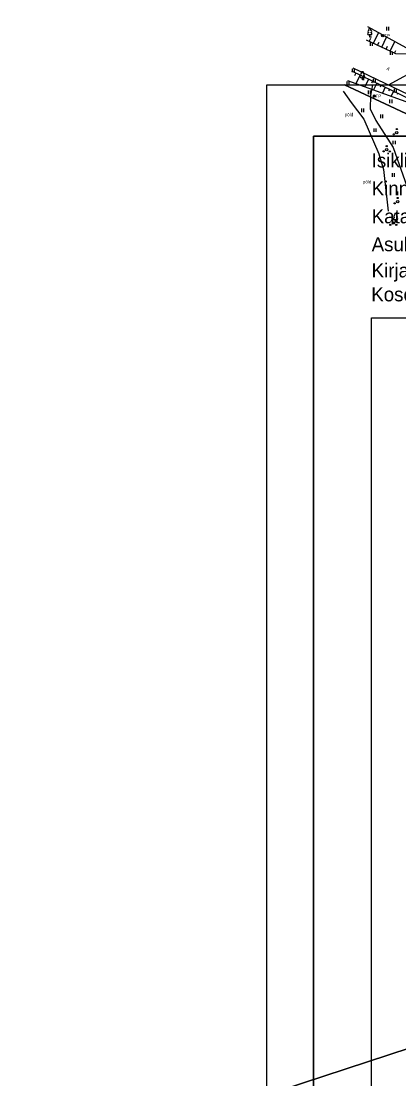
# Model space of a CAD drawing. Extents: x 554947 to 555436, y 6564938 to 6565792.
# Drawn here: x 554946.6 to 555027.7, y 6565441.5 to 6565668.6 of the extents above; entities that cross this region are included whole.
import ezdxf

# ---------------------------------------------------------------- set-up
doc = ezdxf.new("R2010")
doc.units = 0
for name, color, linetype in [('HALJASTUS', 7, 'Continuous'), ('KPKAABEL', 7, 'Continuous'), ('PIIR', 7, 'Continuous'), ('POST', 7, 'Continuous'), ('PUU', 7, 'Continuous'), ('RELJEEF', 7, 'Continuous'), ('TEE', 7, 'Continuous'), ('VORMISTUS_2', 7, 'Continuous')]:
    doc.layers.add(name, color=color, linetype=linetype)

msp = doc.modelspace()

# ---------------------------------------------------------------- linework, layer by layer
at = {"layer": 'HALJASTUS'}
for p, q in [((555025.03, 6565667.38), (555025.03, 6565666.61)), ((555025.49, 6565667.38), (555025.49, 6565666.61)), ((555021.54, 6565664.03), (555021.54, 6565663.27)), ((555021.99, 6565664.03), (555021.99, 6565663.27)), ((555025.82, 6565662.1), (555025.82, 6565661.34)), ((555026.28, 6565662.1), (555026.28, 6565661.34)), ((555017.66, 6565658.36), (555017.66, 6565657.6)), ((555018.12, 6565658.36), (555018.12, 6565657.6)), ((555016.51, 6565655.6), (555016.51, 6565654.84)), ((555016.97, 6565655.6), (555016.97, 6565654.84)), ((555022.17, 6565656.19), (555022.17, 6565655.43)), ((555022.62, 6565656.19), (555022.62, 6565655.43)), ((555021.12, 6565653.67), (555021.12, 6565652.9)), ((555021.58, 6565653.67), (555021.58, 6565652.9)), ((555026.67, 6565654.02), (555026.67, 6565653.26)), ((555027.13, 6565654.02), (555027.13, 6565653.26)), ((555025.73, 6565651.73), (555025.73, 6565650.97)), ((555026.19, 6565651.73), (555026.19, 6565650.97)), ((555019.68, 6565649.8), (555019.68, 6565649.04)), ((555020.14, 6565649.8), (555020.14, 6565649.04)), ((555023.73, 6565648.51), (555023.73, 6565647.75)), ((555024.19, 6565648.51), (555024.19, 6565647.75)), ((555022.32, 6565645.56), (555022.32, 6565644.8)), ((555022.78, 6565645.56), (555022.78, 6565644.8)), ((555026.44, 6565642.9), (555026.44, 6565642.14)), ((555026.89, 6565642.9), (555026.89, 6565642.14)), ((555026.24, 6565635.94), (555026.24, 6565635.18)), ((555026.7, 6565635.94), (555026.7, 6565635.18)), ((555027.44, 6565631.98), (555027.44, 6565631.22))]:
    msp.add_line(p, q, dxfattribs=at)
msp.add_lwpolyline([(555015.75, 6565653.58), (555017.49, 6565651.12), (555020.22, 6565647.57), (555023.44, 6565640.12), (555024.39, 6565636.74), (555025.43, 6565627.79)], dxfattribs=at)
at = {"layer": 'KPKAABEL'}
msp.add_lwpolyline([(555022.08, 6565654.91), (555021.62, 6565652.63), (555021.53, 6565649.77), (555022.79, 6565647.23), (555026.48, 6565641.46), (555030.61, 6565629.73), (555035.38, 6565618.81), (555040.84, 6565608.06), (555047.09, 6565597.8), (555053.57, 6565587.29), (555056.07, 6565583.7), (555062.11, 6565572.67), (555068.25, 6565560.98), (555073.77, 6565549.85), (555080.11, 6565537.98), (555085.96, 6565527.61), (555092.4, 6565515.61), (555098.4, 6565504.54), (555104.64, 6565492.44), (555110.84, 6565480.82), (555116.7, 6565469.07), (555121.82, 6565458.12), (555126.89, 6565446.73), (555132.74, 6565435.39)], dxfattribs=at)
at = {"layer": 'PIIR'}
for points in [[(555016.05, 6565654.91), (555030.24, 6565648.23), (555043.11, 6565640.11), (555053.62, 6565632.14), (555056.61, 6565622.91), (555057.22, 6565600.73), (555060.42, 6565583.26), (555065.78, 6565566.7), (555076.76, 6565542.38), (555113.82, 6565475.68), (554946.63, 6565420.78), (554981.01, 6565316.76), (555160.07, 6565375.54), (555166.64, 6565360.5), (555167.67, 6565357.91)], [(555045.31, 6565654.91), (555047.17, 6565654.02), (555063.43, 6565647.29), (555056.61, 6565622.91), (555053.62, 6565632.14), (555043.11, 6565640.11), (555030.24, 6565648.23), (555016.05, 6565654.91)]]:
    msp.add_lwpolyline(points, dxfattribs=at)
msp.add_lwpolyline([(554981.01, 6565316.76), (554946.63, 6565420.78), (555113.82, 6565475.68), (555124.27, 6565454.45), (555144.16, 6565410.6), (555160.07, 6565375.54)], close=True, dxfattribs=at)
at = {"layer": 'POST'}
for centre, radius in [((555024.26, 6565665.45), 0.25), ((555024.26, 6565665.45), 0.225), ((555024.26, 6565665.45), 0.2), ((555024.26, 6565665.45), 0.175), ((555024.26, 6565665.45), 0.15), ((555024.26, 6565665.45), 0.125), ((555024.26, 6565665.45), 0.1), ((555024.26, 6565665.45), 0.075), ((555024.26, 6565665.45), 0.05), ((555024.26, 6565665.45), 0.025), ((555022.42, 6565652.48), 0.25), ((555022.42, 6565652.48), 0.225), ((555022.42, 6565652.48), 0.2), ((555022.42, 6565652.48), 0.175), ((555022.42, 6565652.48), 0.15), ((555022.42, 6565652.48), 0.125), ((555022.42, 6565652.48), 0.1), ((555022.42, 6565652.48), 0.075), ((555022.42, 6565652.48), 0.05), ((555022.42, 6565652.48), 0.025)]:
    msp.add_circle(centre, radius, dxfattribs=at)
at = {"layer": 'PUU'}
for p, q in [((555021.71, 6565665.65), (555021.23, 6565665.65)), ((555021.47, 6565665.17), (555021.47, 6565665.65)), ((555021.85, 6565665.17), (555021.47, 6565665.17)), ((555020.13, 6565656.42), (555019.65, 6565656.42)), ((555019.89, 6565655.95), (555019.89, 6565656.42)), ((555020.27, 6565655.95), (555019.89, 6565655.95)), ((555027.24, 6565625.93), (555026.76, 6565625.93)), ((555027, 6565625.46), (555027, 6565625.93)), ((555027.38, 6565625.46), (555027, 6565625.46))]:
    msp.add_line(p, q, dxfattribs=at)
for centre, radius in [((555027.26, 6565645.42), 0.125), ((555026.61, 6565644.3), 0.125), ((555027.26, 6565644.67), 0.25), ((555025.1, 6565640.99), 0.25), ((555025.1, 6565641.74), 0.125), ((555024.45, 6565640.62), 0.125), ((555025.75, 6565640.62), 0.125), ((555026.8, 6565629.48), 0.125), ((555027.45, 6565629.85), 0.25), ((555027.45, 6565630.6), 0.125), ((555026.51, 6565625.25), 0.25), ((555026.51, 6565626), 0.125), ((555025.86, 6565624.87), 0.125), ((555027.16, 6565624.87), 0.125)]:
    msp.add_circle(centre, radius, dxfattribs=at)
for centre, radius, start, end in [((555021.23, 6565665.88), 0.238, 90.0016, 269.3953), ((555021.3, 6565666.34), 0.233, 109.0217, 253.1415), ((555021.47, 6565666.69), 0.277, 332.5799, 207.4201), ((555021.64, 6565666.34), 0.233, 286.8508, 70.9859), ((555021.7, 6565665.88), 0.238, 270.6047, 89.9984), ((555019.65, 6565656.66), 0.238, 90.0016, 269.3953), ((555019.72, 6565657.12), 0.233, 109.0217, 253.1415), ((555019.89, 6565657.46), 0.277, 332.5799, 207.4201), ((555020.06, 6565657.12), 0.233, 286.8508, 70.9859), ((555020.13, 6565656.66), 0.238, 270.6047, 89.9984), ((555026.76, 6565626.17), 0.238, 90.0016, 269.3953), ((555026.83, 6565626.63), 0.233, 109.0217, 253.1415), ((555027, 6565626.98), 0.277, 332.5799, 207.4201), ((555027.17, 6565626.63), 0.233, 286.8508, 70.9859), ((555027.24, 6565626.17), 0.238, 270.6047, 89.9984)]:
    msp.add_arc(centre, radius, start, end, dxfattribs=at)
at = {"layer": 'RELJEEF'}
for p, q in [((555022.24, 6565663.83), (555023.31, 6565666.1)), ((555021.34, 6565664.25), (555021.66, 6565664.95)), ((555023.15, 6565663.4), (555023.46, 6565664.07)), ((555024.06, 6565662.98), (555025.07, 6565665.15)), ((555025.87, 6565662.13), (555026.83, 6565664.2)), ((555024.96, 6565662.56), (555025.26, 6565663.19)), ((555026.78, 6565661.71), (555027.06, 6565662.31)), ((555025.49, 6565654.91), (555036.81, 6565661.16)), ((555018.47, 6565657.45), (555018.19, 6565656.87)), ((555019.37, 6565657.02), (555018.48, 6565655.17)), ((555020.27, 6565656.58), (555020.02, 6565656.06)), ((555021.17, 6565656.15), (555020.37, 6565654.49)), ((555022.07, 6565655.72), (555021.85, 6565655.25)), ((555022.97, 6565655.28), (555022.26, 6565653.81)), ((555023.87, 6565654.85), (555023.67, 6565654.44)), ((555024.77, 6565654.41), (555024.16, 6565653.13)), ((555025.67, 6565653.98), (555025.5, 6565653.62)), ((555026.58, 6565653.55), (555026.05, 6565652.45)), ((555027.48, 6565653.11), (555027.33, 6565652.81))]:
    msp.add_line(p, q, dxfattribs=at)
for points in [[(555029.78, 6565668.58), (555030.58, 6565661.46), (555027.05, 6565661.58), (555020.79, 6565664.51)], [(555029.78, 6565668.58), (555030.08, 6565662.44), (555021.01, 6565667.34)], [(555017.57, 6565657.89), (555030.59, 6565651.61), (555041.81, 6565645.02), (555049.4, 6565639.13)], [(555016.65, 6565655.83), (555029.97, 6565651.05), (555041.06, 6565644.31), (555048.71, 6565638.55)]]:
    msp.add_lwpolyline(points, dxfattribs=at)
at = {"layer": 'TEE'}
msp.add_lwpolyline([(555017.83, 6565658.57), (555031.54, 6565651.99), (555031.85, 6565651.41), (555035.2, 6565649.62), (555035.88, 6565649.68), (555042.56, 6565645.53), (555050.24, 6565639.61)], dxfattribs=at)
at = {"layer": 'VORMISTUS_2'}
for points in [[(554999.36, 6565654.91), (555209.36, 6565654.91), (555209.36, 6565357.91), (554999.36, 6565357.91)], [(555009.36, 6565368.91), (555199.36, 6565368.91), (555199.36, 6565643.91), (555009.36, 6565643.91)], [(555009.36, 6565643.91), (555199.36, 6565643.91), (555199.36, 6565368.91), (555009.36, 6565368.91)], [(555186.86, 6565394.91), (555021.86, 6565394.91), (555021.86, 6565604.91), (555186.86, 6565604.91)]]:
    msp.add_lwpolyline(points, close=True, dxfattribs=at)

# ---------------------------------------------------------------- texts
at = {"layer": 'HALJASTUS'}
for p in [(555016.07, 6565648.17), (555019.98, 6565633.75)]:
    msp.add_text('põld', height=0.7, rotation=359.9544, dxfattribs=at).set_placement(p)
at = {"layer": 'POST'}
for p in [(555024.26, 6565665.1), (555022.42, 6565652.13)]:
    msp.add_text(' TP', height=0.7, dxfattribs=at).set_placement(p)
at = {"layer": 'TEE'}
msp.add_text('A', height=0.7, rotation=333.5713, dxfattribs=at).set_placement((555025, 6565658.19))
at = {"layer": 'VORMISTUS_2'}
for s, p in [('Isikliku kasutusõiguse asendiplaan', (555021.87, 6565637.18)), ('Kinnistu nimi: 11202 Vaida-Urge tee', (555021.87, 6565631.18)), ('Katastritunnus: 33701:001:0541', (555021.87, 6565625.18)), ('Asukoht: Tuhala küla, Kose vald, Harju maakond', (555021.87, 6565619.18))]:
    msp.add_text(s, height=3, dxfattribs=at).set_placement(p)
for s, p in [('Kirjanurk OÜ töö nr 10379P', (555021.86, 6565613.57)), ('Kose vald, Tuhala ja Otiveski elurajooni sideühendus', (555021.78, 6565608.43))]:
    msp.add_text(s, height=3, rotation=360, dxfattribs=at).set_placement(p)

doc.saveas('drawing.dxf')
